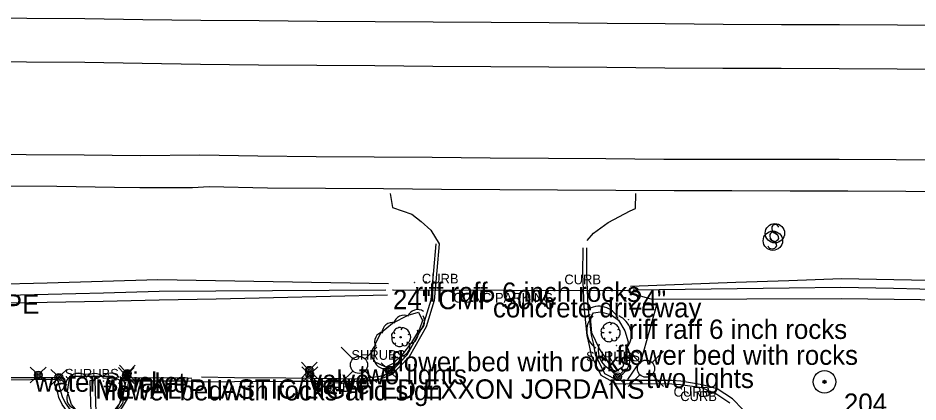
# Model space of a CAD drawing. Extents: x 1802180 to 1804859, y 572524 to 575172.
# Drawn here: x 1803724.4 to 1803957, y 573717 to 573816.1 of the extents above; entities that cross this region are included whole.
import ezdxf

# ---------------------------------------------------------------- set-up
doc = ezdxf.new("R2010")
doc.units = 0
for name, color, linetype in [('EX_EDGE_PAVEMENT', 7, 'Continuous'), ('EX_SHOULDER', 7, 'Continuous'), ('S_CURB', 7, 'Continuous'), ('S_CURB_ANNOT', 7, 'Continuous'), ('S_DITCHLINE', 7, 'Continuous'), ('S_DRG_PT_SYM', 7, 'Continuous'), ('S_IRON_PIN', 7, 'Continuous'), ('S_IRON_PIN_ANNOT', 7, 'Continuous'), ('S_MSC_PT_SYM', 7, 'Continuous'), ('S_PARKING', 7, 'Continuous'), ('S_PARKING_ANNOT', 7, 'Continuous'), ('S_PAVEMENT_CROWN', 7, 'Continuous'), ('S_SIDE_DRAIN', 7, 'Continuous'), ('S_SIDE_DRAIN_ANNOT', 7, 'Continuous'), ('S_SIGN', 7, 'Continuous'), ('S_SIGN_ANNOT', 7, 'Continuous'), ('S_SPRINKLER_HEAD', 7, 'Continuous'), ('S_SPRINKLER_HEAD_ANNOT', 7, 'Continuous'), ('S_SURVEY_TEXT_ANNOT', 7, 'Continuous'), ('S_TREE', 7, 'Continuous'), ('S_TREE_ANNOT', 7, 'Continuous'), ('S_UTILITY_POLE', 7, 'Continuous'), ('S_UTILITY_POLE_ANNOT', 7, 'Continuous')]:
    doc.layers.add(name, color=color, linetype=linetype)

msp = doc.modelspace()

# ---------------------------------------------------------------- linework, layer by layer
at = {"layer": 'EX_EDGE_PAVEMENT'}
msp.add_lwpolyline([(1803966.35, 573779.29), (1803951.36, 573779.48), (1803936.57, 573779.54), (1803921.57, 573779.58), (1803906.3, 573779.62), (1803891.3, 573779.61), (1803876.3, 573779.72), (1803861.44, 573779.87), (1803846.44, 573779.93), (1803831.45, 573780.06), (1803816.41, 573780.16), (1803801.41, 573780.27), (1803786.33, 573780.4), (1803771.33, 573780.72), (1803755.94, 573780.54), (1803741.44, 573780.69), (1803726.44, 573780.8), (1803711.44, 573780.89)], dxfattribs=at)
at = {"layer": 'EX_SHOULDER'}
for points in [[(1803508.95, 573775.06), (1803514.58, 573774.6), (1803516.31, 573774.59), (1803531.3, 573774.54), (1803546.3, 573774.46), (1803554.44, 573774.34), (1803569.39, 573774.05), (1803584.41, 573773.96), (1803599.4, 573774.12), (1803614.28, 573774.18), (1803629.34, 573773.92), (1803644.48, 573773.93), (1803659.36, 573773.87), (1803674.34, 573773.21), (1803689.36, 573773.01), (1803704.37, 573772.88), (1803719.38, 573772.78), (1803734.37, 573772.68), (1803749.34, 573772.46), (1803755.85, 573772.35), (1803769.43, 573772.35)], [(1803769.43, 573772.35), (1803773.74, 573772.62), (1803788.86, 573772.3), (1803803.86, 573772.17), (1803818.86, 573772.06), (1803833.85, 573771.95), (1803848.89, 573771.84), (1803863.84, 573771.76), (1803878.86, 573771.63), (1803893.93, 573771.54), (1803908.9, 573771.53), (1803923.9, 573771.49), (1803938.88, 573771.45), (1803953.82, 573771.37), (1803968.84, 573771.16), (1803983.86, 573771.02), (1803998.87, 573770.92), (1804013.89, 573770.83), (1804028.91, 573770.79), (1804043.8, 573770.75), (1804058.91, 573770.56), (1804073.7, 573770.51), (1804088.8, 573770.06)]]:
    msp.add_lwpolyline(points, dxfattribs=at)
at = {"layer": 'S_CURB'}
for points in [[(1803734.26, 573723.19), (1803721.06, 573723.16), (1803706.06, 573723.41), (1803697.3, 573723.24), (1803686.91, 573723.26), (1803671.91, 573723.29), (1803666.26, 573724.25), (1803659.88, 573726.28), (1803656.45, 573730.69), (1803653.84, 573736.77), (1803652.7, 573745.75), (1803652.36, 573757.72), (1803652.87, 573761.27), (1803656.21, 573764.9), (1803659.13, 573767.17), (1803663.86, 573769.14)], [(1803771.77, 573723.42), (1803780.34, 573723.29), (1803793.63, 573723.18), (1803807.28, 573723), (1803812.71, 573722.96), (1803817.98, 573723.66), (1803820.52, 573724.5), (1803824.97, 573729.14), (1803829.11, 573736.58), (1803831.15, 573743.36), (1803831.85, 573750.95), (1803832.41, 573757.83)], [(1803911.72, 573714.98), (1803909.06, 573717.79), (1803905.04, 573720.34), (1803901.22, 573721.42), (1803895.65, 573722.29), (1803893.35, 573722.47), (1803879.41, 573722.54), (1803876.03, 573724.25), (1803873.65, 573729.16), (1803873.17, 573731.78), (1803872.59, 573734.21), (1803871.73, 573741.62), (1803871.38, 573750.05), (1803871.37, 573756.78)], [(1803752.29, 573723.18), (1803767.31, 573723.3), (1803769.32, 573723.14)], [(1803734.62, 573722.43), (1803735.41, 573719.52), (1803735.75, 573718.35), (1803736.57, 573716.76), (1803738.74, 573713.7), (1803742.42, 573711.82), (1803744.94, 573711.94), (1803748.4, 573713.52), (1803750.46, 573716.24), (1803751.49, 573718), (1803752.22, 573722.06)]]:
    msp.add_lwpolyline(points, dxfattribs=at)
at = {"layer": 'S_DITCHLINE'}
for points in [[(1803882.65, 573746.87), (1803896.29, 573747.37), (1803909.93, 573747.87), (1803923.57, 573748.37), (1803937.21, 573748.87), (1803950.77, 573748.6), (1803964.33, 573748.34), (1803977.89, 573748.08), (1803991.46, 573747.82), (1804004.3, 573747.89), (1804017.14, 573747.96), (1804029.98, 573748.03), (1804042.82, 573748.1), (1804055.51, 573747.26), (1804068.19, 573746.41), (1804080.87, 573745.57), (1804093.55, 573744.72)], [(1803820.1, 573747.45), (1803805.21, 573747.71), (1803790.31, 573747.98), (1803775.41, 573748.24), (1803760.52, 573748.5), (1803746.2, 573748.09), (1803731.89, 573747.68), (1803717.57, 573747.26), (1803703.26, 573746.85), (1803683.48, 573746.78), (1803663.69, 573746.71)], [(1803883.34, 573745.94), (1803896.78, 573746.11), (1803910.21, 573746.28), (1803923.64, 573746.45), (1803937.07, 573746.63), (1803950.66, 573746.32), (1803964.25, 573746.01), (1803977.84, 573745.7), (1803991.43, 573745.39), (1804004.36, 573745.3), (1804017.29, 573745.21), (1804030.22, 573745.12), (1804043.14, 573745.03), (1804068.08, 573744.41), (1804093.03, 573743.79)], [(1803819.88, 573744.5), (1803805.12, 573744.19), (1803790.36, 573743.87), (1803775.6, 573743.55), (1803760.83, 573743.24), (1803746.39, 573742.94), (1803731.94, 573742.65), (1803717.49, 573742.35), (1803703.05, 573742.06), (1803683.66, 573742.88), (1803664.28, 573743.7)], [(1803819.4, 573745.84), (1803804.76, 573745.74), (1803790.13, 573745.65), (1803775.5, 573745.56), (1803760.86, 573745.46), (1803746.5, 573745.1), (1803732.14, 573744.73), (1803717.78, 573744.37), (1803703.42, 573744.01), (1803683.93, 573744.61), (1803664.45, 573745.21)], [(1803882.8, 573745.02), (1803888.17, 573743.49), (1803912.71, 573743.6), (1803937.24, 573743.71), (1803950.82, 573743.54), (1803964.39, 573743.37), (1803977.96, 573743.2), (1803991.54, 573743.02), (1804004.37, 573742.8), (1804017.21, 573742.57), (1804030.05, 573742.35), (1804042.88, 573742.12), (1804055.57, 573742.23), (1804068.26, 573742.33), (1804080.95, 573742.44), (1804093.63, 573742.54)], [(1803881.95, 573722.8), (1803885.48, 573727.96), (1803889.5, 573742.02)]]:
    msp.add_lwpolyline(points, dxfattribs=at)
at = {"layer": 'S_DRG_PT_SYM'}
for points in [[(1803821.27, 573745.91), (1803821.27, 573745.96), (1803821.27, 573745.91), (1803821.22, 573745.91), (1803821.27, 573745.91), (1803821.27, 573745.86), (1803821.27, 573745.91), (1803821.32, 573745.91)], [(1803882.07, 573745.77), (1803882.07, 573745.82), (1803882.07, 573745.77), (1803882.02, 573745.77), (1803882.07, 573745.77), (1803882.07, 573745.72), (1803882.07, 573745.77), (1803882.12, 573745.77)]]:
    msp.add_lwpolyline(points, dxfattribs=at)
at = {"layer": 'S_IRON_PIN'}
for radius in [2.91, 0.411, 0.262, 0.212, 0.145, 0.0822, 0.0581]:
    msp.add_circle((1803932.82, 573722.15), radius, dxfattribs=at)
at = {"layer": 'S_MSC_PT_SYM'}
for points in [[(1803826.82, 573747.82), (1803826.82, 573747.87), (1803826.82, 573747.82), (1803826.77, 573747.82), (1803826.82, 573747.82), (1803826.82, 573747.77), (1803826.82, 573747.82), (1803826.87, 573747.82)], [(1803847.12, 573743.8), (1803847.12, 573743.85), (1803847.12, 573743.8), (1803847.07, 573743.8), (1803847.12, 573743.8), (1803847.12, 573743.75), (1803847.12, 573743.8), (1803847.17, 573743.8)], [(1803882.18, 573738.24), (1803882.18, 573738.29), (1803882.18, 573738.24), (1803882.13, 573738.24), (1803882.18, 573738.24), (1803882.18, 573738.19), (1803882.18, 573738.24), (1803882.23, 573738.24)], [(1803879.04, 573731.55), (1803879.04, 573731.6), (1803879.04, 573731.55), (1803878.99, 573731.55), (1803879.04, 573731.55), (1803879.04, 573731.5), (1803879.04, 573731.55), (1803879.09, 573731.55)], [(1803820.72, 573729.86), (1803820.72, 573729.91), (1803820.72, 573729.86), (1803820.67, 573729.86), (1803820.72, 573729.86), (1803820.72, 573729.81), (1803820.72, 573729.86), (1803820.77, 573729.86)], [(1803728.7, 573724.59), (1803728.7, 573724.64), (1803728.7, 573724.59), (1803728.65, 573724.59), (1803728.7, 573724.59), (1803728.7, 573724.54), (1803728.7, 573724.59), (1803728.75, 573724.59)], [(1803744.35, 573722.8), (1803744.35, 573722.85), (1803744.35, 573722.8), (1803744.3, 573722.8), (1803744.35, 573722.8), (1803744.35, 573722.75), (1803744.35, 573722.8), (1803744.4, 573722.8)], [(1803746.44, 573722.36), (1803746.44, 573722.41), (1803746.44, 573722.36), (1803746.39, 573722.36), (1803746.44, 573722.36), (1803746.44, 573722.31), (1803746.44, 573722.36), (1803746.49, 573722.36)]]:
    msp.add_lwpolyline(points, dxfattribs=at)
at = {"layer": 'S_PARKING'}
for points in [[(1803734.26, 573722.73), (1803721.05, 573722.61), (1803706.08, 573722.69), (1803697.3, 573722.48), (1803686.91, 573722.63), (1803671.8, 573722.68), (1803665.93, 573723.25), (1803659.23, 573725.79), (1803655.81, 573730.2), (1803653.17, 573736.5), (1803651.97, 573745.68), (1803651.65, 573757.71), (1803651.9, 573760.39), (1803652.12, 573761.37), (1803655.69, 573765.38), (1803658.73, 573767.69), (1803664.04, 573769.76), (1803664.33, 573772.53)], [(1803820.52, 573770.79), (1803821.18, 573767.21), (1803826.12, 573765.42), (1803828.59, 573763.58), (1803831.04, 573761.35), (1803833.22, 573757.77), (1803832.65, 573750.89), (1803831.92, 573743.14), (1803829.83, 573736.38), (1803825.5, 573728.64), (1803821.04, 573724.01), (1803818.08, 573722.87), (1803812.81, 573722.16), (1803807.27, 573722.22), (1803793.62, 573722.26), (1803780.33, 573722.15), (1803771.74, 573722.07), (1803769.24, 573722.24), (1803767.73, 573722.29), (1803752.82, 573722.31), (1803752.77, 573720.94), (1803752.57, 573717.81), (1803751.31, 573715.59)], [(1803820.52, 573770.79), (1803821.18, 573767.21), (1803826.12, 573765.42), (1803828.59, 573763.58), (1803831.04, 573761.35), (1803833.22, 573757.77)], [(1803871.44, 573758.7), (1803873.08, 573760.57), (1803876.89, 573763.31), (1803882.59, 573766.33), (1803883.96, 573766.89), (1803884.08, 573770.79)], [(1803871.44, 573758.7), (1803873.08, 573760.57), (1803876.89, 573763.31), (1803882.59, 573766.33), (1803883.96, 573766.89), (1803884.08, 573770.79)], [(1803833.22, 573757.77), (1803832.65, 573750.89), (1803831.92, 573743.14), (1803829.83, 573736.38), (1803825.5, 573728.64), (1803821.04, 573724.01), (1803818.08, 573722.87), (1803812.81, 573722.16), (1803807.27, 573722.22), (1803793.62, 573722.26), (1803780.33, 573722.15), (1803771.74, 573722.07)], [(1803908.32, 573716.62), (1803904.69, 573719.08), (1803901.1, 573720.62), (1803895.58, 573721.39), (1803893.36, 573721.54), (1803878.94, 573721.66), (1803875.07, 573723.81), (1803872.63, 573729), (1803872.09, 573731.56), (1803871.47, 573734.1), (1803870.73, 573741.59), (1803870.39, 573750.06), (1803870.43, 573756.78)], [(1803908.32, 573716.62), (1803904.69, 573719.08), (1803901.1, 573720.62), (1803895.58, 573721.39), (1803893.36, 573721.54), (1803878.94, 573721.66), (1803875.07, 573723.81), (1803872.63, 573729), (1803872.09, 573731.56), (1803871.47, 573734.1), (1803870.73, 573741.59), (1803870.39, 573750.06), (1803870.43, 573756.78)], [(1803735.79, 573716.34), (1803734.96, 573718.12), (1803734.66, 573719.3), (1803733.8, 573721.64), (1803734.26, 573722.73), (1803721.05, 573722.61)], [(1803752.77, 573720.94), (1803752.57, 573717.81), (1803751.31, 573715.59), (1803749.22, 573712.89), (1803744.96, 573711.13), (1803742.43, 573710.89), (1803738.32, 573712.87), (1803735.79, 573716.34), (1803734.96, 573718.12), (1803734.66, 573719.3), (1803733.8, 573721.64), (1803734.26, 573722.73)], [(1803771.74, 573722.07), (1803769.24, 573722.24), (1803767.73, 573722.29), (1803752.82, 573722.31), (1803752.77, 573720.94)]]:
    msp.add_lwpolyline(points, dxfattribs=at)
at = {"layer": 'S_PAVEMENT_CROWN'}
for points in [[(1803966.66, 573814.15), (1803951.66, 573814.28), (1803936.66, 573814.34), (1803921.66, 573814.38), (1803906.66, 573814.43), (1803891.66, 573814.58), (1803876.66, 573814.73), (1803861.66, 573814.86), (1803846.66, 573814.95), (1803831.66, 573815.05), (1803816.66, 573815.15), (1803801.66, 573815.26), (1803786.66, 573815.37), (1803771.66, 573815.52), (1803756.67, 573815.66), (1803741.67, 573815.93), (1803726.67, 573816.02), (1803711.67, 573816.12)], [(1803711.6, 573804.93), (1803726.6, 573804.83), (1803741.6, 573804.7), (1803756.43, 573804.47), (1803771.56, 573804.16), (1803786.56, 573804.06), (1803801.58, 573803.94), (1803816.58, 573803.83), (1803831.59, 573803.72), (1803846.59, 573803.6), (1803861.59, 573803.54), (1803876.55, 573803.39), (1803891.54, 573803.23), (1803906.54, 573803.17), (1803921.63, 573803.13), (1803936.63, 573803.09), (1803951.56, 573803.03), (1803966.56, 573802.86)]]:
    msp.add_lwpolyline(points, dxfattribs=at)
at = {"layer": 'S_SIDE_DRAIN'}
msp.add_line((1803821.27, 573745.91), (1803882.07, 573745.77), dxfattribs=at)
at = {"layer": 'S_SIGN'}
msp.add_lwpolyline([(1803744.22, 573722.6), (1803744.45, 573714.23), (1803743.24, 573714.21), (1803743.03, 573722.52), (1803744.22, 573722.6)], dxfattribs=at)
for centre in [(1803919.99, 573760.54), (1803919.47, 573758.6)]:
    msp.add_circle(centre, 2.5, dxfattribs=at)
for centre, radius, start, end in [((1803920.07, 573761.81), 0.952, 16.5258, 156.8957), ((1803920.15, 573759.93), 1.51, 167.1196, 241.9813), ((1803919.54, 573759.87), 0.952, 16.5258, 156.8957), ((1803920.68, 573761.87), 1.51, 167.1196, 241.9813), ((1803919.58, 573759.2), 1.4, 358.6529, 73.7063), ((1803919.84, 573759.72), 1.28, 204.641, 335.359), ((1803919.05, 573757.26), 1.4, 358.6529, 73.7063), ((1803919.31, 573757.78), 1.28, 204.641, 335.359)]:
    msp.add_arc(centre, radius, start, end, dxfattribs=at)
at = {"layer": 'S_SPRINKLER_HEAD'}
for p, q in [((1803728.89, 573724.62), (1803727.55, 573725.97)), ((1803730.29, 573724.62), (1803731.64, 573725.97)), ((1803734.22, 573724.04), (1803732.87, 573725.38)), ((1803735.62, 573724.04), (1803736.96, 573725.38)), ((1803751.64, 573724.51), (1803750.3, 573725.85)), ((1803751.93, 573725.08), (1803750.59, 573726.42)), ((1803753.05, 573724.51), (1803754.39, 573725.85)), ((1803753.34, 573725.08), (1803754.68, 573726.42)), ((1803798.94, 573725.86), (1803797.6, 573727.21)), ((1803799.08, 573724.71), (1803797.73, 573726.06)), ((1803800.35, 573725.86), (1803801.69, 573727.21)), ((1803800.48, 573724.71), (1803801.82, 573726.06)), ((1803819.61, 573725.75), (1803818.26, 573727.09)), ((1803821.01, 573725.75), (1803822.35, 573727.09)), ((1803878.62, 573724.17), (1803877.28, 573725.51)), ((1803880.03, 573724.17), (1803881.37, 573725.51)), ((1803728.89, 573723.22), (1803727.55, 573721.88)), ((1803730.29, 573723.22), (1803731.64, 573721.88)), ((1803751.64, 573723.11), (1803750.3, 573721.76)), ((1803751.93, 573723.67), (1803750.59, 573722.33)), ((1803753.05, 573723.11), (1803754.39, 573721.76)), ((1803753.34, 573723.67), (1803754.68, 573722.33)), ((1803798.94, 573724.46), (1803797.6, 573723.12)), ((1803799.08, 573723.31), (1803797.73, 573721.96)), ((1803800.35, 573724.46), (1803801.69, 573723.12)), ((1803800.48, 573723.31), (1803801.82, 573721.96)), ((1803819.61, 573724.34), (1803818.26, 573723)), ((1803821.01, 573724.34), (1803822.35, 573723)), ((1803734.22, 573722.64), (1803732.87, 573721.29)), ((1803735.62, 573722.64), (1803736.96, 573721.29)), ((1803878.62, 573722.76), (1803877.28, 573721.42)), ((1803880.03, 573722.76), (1803881.37, 573721.42))]:
    msp.add_line(p, q, dxfattribs=at)
for centre, radius in [((1803752.64, 573724.38), 0.994), ((1803799.64, 573725.16), 0.994), ((1803799.64, 573725.16), 0.634), ((1803799.64, 573725.16), 0.274), ((1803820.31, 573725.04), 0.994), ((1803820.31, 573725.04), 0.634), ((1803729.59, 573723.92), 0.994), ((1803729.59, 573723.92), 0.634), ((1803729.59, 573723.92), 0.274), ((1803734.92, 573723.34), 0.994), ((1803734.92, 573723.34), 0.634), ((1803734.92, 573723.34), 0.274), ((1803752.35, 573723.81), 0.994), ((1803752.35, 573723.81), 0.634), ((1803752.64, 573724.38), 0.634), ((1803752.35, 573723.81), 0.274), ((1803752.64, 573724.38), 0.274), ((1803799.78, 573724.01), 0.994), ((1803799.78, 573724.01), 0.634), ((1803799.78, 573724.01), 0.274), ((1803820.31, 573725.04), 0.274), ((1803879.32, 573723.46), 0.994), ((1803879.32, 573723.46), 0.634), ((1803879.32, 573723.46), 0.274)]:
    msp.add_circle(centre, radius, dxfattribs=at)
at = {"layer": 'S_TREE'}
for p, q in [((1803877.7, 573737.26), (1803877.48, 573736.79)), ((1803821.46, 573734.9), (1803821.74, 573734.58)), ((1803823.55, 573736.02), (1803823.34, 573735.55)), ((1803875.24, 573734.86), (1803875.86, 573734.86)), ((1803875.6, 573736.15), (1803875.88, 573735.82)), ((1803879.66, 573735.72), (1803879.3, 573735.57)), ((1803821.1, 573733.62), (1803821.72, 573733.62)), ((1803825.09, 573732.21), (1803824.84, 573732.45)), ((1803825.52, 573734.48), (1803825.16, 573734.33)), ((1803875.88, 573733.11), (1803876.13, 573733.49)), ((1803877.91, 573732.96), (1803877.87, 573733.39)), ((1803879.23, 573733.45), (1803878.98, 573733.69)), ((1803821.74, 573731.87), (1803821.99, 573732.25)), ((1803823.77, 573731.72), (1803823.73, 573732.15))]:
    msp.add_line(p, q, dxfattribs=at)
for points in [[(1803816.34, 573727.42), (1803816.65, 573731.85), (1803818.23, 573734.92), (1803821.14, 573737.31), (1803825.22, 573739.36), (1803827.84, 573740.19), (1803828.93, 573737.96), (1803828.17, 573735.76), (1803826.04, 573732.34), (1803823.6, 573729.01), (1803821.29, 573726.89), (1803819.45, 573725.97), (1803816.34, 573727.42)], [(1803878.55, 573724.57), (1803876.46, 573728.05), (1803874.67, 573730.71), (1803872.71, 573734.79), (1803872.34, 573738.75), (1803873.11, 573739.96), (1803874.92, 573740.27), (1803877.55, 573739.56), (1803879.54, 573738.11), (1803881.24, 573735.32), (1803882.03, 573732.48), (1803880.73, 573726.05), (1803878.55, 573724.57)], [(1803737.79, 573723.61), (1803748.81, 573723.59), (1803751.1, 573722.32), (1803751.47, 573719.6), (1803750.62, 573716.58), (1803749.13, 573713.9), (1803742.37, 573713.13), (1803739.74, 573714.49), (1803738.18, 573716.29), (1803737.12, 573719.64), (1803737.79, 573723.61)]]:
    msp.add_lwpolyline(points, dxfattribs=at)
for centre in [(1803877.39, 573734.91), (1803823.25, 573733.67)]:
    msp.add_circle(centre, 0.188, dxfattribs=at)
for centre, radius, start, end in [((1803874.56, 573736.32), 5.35, 23.9843, 125.5812), ((1803824.19, 573736.63), 2.74, 65.8801, 167.4771), ((1803827.67, 573738.07), 2.74, 56.8574, 158.4543), ((1803821.2, 573734.77), 2.74, 78.5236, 180.1205), ((1803826.73, 573737.72), 2.74, 290.1168, 31.7137), ((1803876.69, 573735.35), 5.35, 134.5266, 236.1235), ((1803877.53, 573734.26), 5.35, 324.8119, 66.4088), ((1803819.25, 573732.41), 2.74, 102.0316, 203.6285), ((1803825.04, 573734.62), 2.74, 277.2267, 18.8236), ((1803818.48, 573729.39), 2.74, 125.1156, 226.7125), ((1803822.91, 573731.45), 2.74, 273.0458, 14.6427), ((1803879.65, 573730.3), 5.35, 163.0331, 264.63), ((1803877.25, 573728.28), 5.35, 297.8039, 39.4008), ((1803820.49, 573728.82), 2.74, 261.7777, 3.3746), ((1803819.09, 573728.31), 2.74, 194.279, 295.8759), ((1803739.45, 573721.09), 2.85, 119.6904, 221.2873), ((1803739.99, 573721.53), 2.85, 39.1092, 140.7061), ((1803744.17, 573721.46), 2.85, 39.1092, 140.7061), ((1803748.3, 573721.51), 2.85, 39.1092, 140.7061), ((1803749.2, 573721.03), 2.85, 316.7937, 58.3907), ((1803739.81, 573717.93), 2.85, 146.6596, 248.2565), ((1803748.8, 573717.71), 2.85, 293.6114, 35.2083)]:
    msp.add_arc(centre, radius, start, end, dxfattribs=at)
for centre, major_axis, ratio, start_param, end_param in [((1803876.65, 573736.68), (1.02, 0.6), 0.471018, 0, 3.141593), ((1803878.67, 573736.5), (-1, 0.75), 0.405113, 3.141593, 6.283186), ((1803821.28, 573734.27), (0.168, 0.567), 0.646762, 0, 3.141593), ((1803822.51, 573735.44), (1.02, 0.6), 0.471018, 0, 3.141593), ((1803824.53, 573735.26), (-1, 0.75), 0.405113, 3.141593, 6.283186), ((1803875.42, 573735.51), (0.168, 0.567), 0.646762, 0, 3.141593), ((1803875.59, 573734.05), (-0.337, 0.88), 0.420543, 6.283185, 9.424777), ((1803879.41, 573734.62), (0.25, 1.13), 0.482994, 3.141593, 6.283185), ((1803821.45, 573732.81), (-0.337, 0.88), 0.420543, 6.283185, 9.424777), ((1803825.27, 573733.38), (0.25, 1.13), 0.482994, 3.141593, 6.283185), ((1803876.94, 573733.07), (-1.01, 0.11), 0.529943, 0, 3.141593), ((1803878.57, 573733.23), (0.602, 0.255), 0.711534, 3.141592, 6.283185), ((1803822.8, 573731.83), (-1.01, 0.11), 0.529943, 0, 3.141593), ((1803824.43, 573731.99), (0.602, 0.255), 0.711534, 3.141592, 6.283185)]:
    msp.add_ellipse(centre, major_axis=major_axis, ratio=ratio, start_param=start_param, end_param=end_param, dxfattribs=at)
at = {"layer": 'S_UTILITY_POLE'}
for p, q in [((1803810.91, 573728.11), (1803807.92, 573731.09)), ((1803814.09, 573728.11), (1803817.07, 573731.09)), ((1803885.08, 573727.14), (1803882.1, 573730.12)), ((1803888.26, 573727.14), (1803891.24, 573730.12)), ((1803810.91, 573724.93), (1803807.92, 573721.95)), ((1803814.09, 573724.93), (1803817.07, 573721.95)), ((1803885.08, 573723.96), (1803882.1, 573720.98)), ((1803888.26, 573723.96), (1803891.24, 573720.98))]:
    msp.add_line(p, q, dxfattribs=at)
for centre in [(1803812.5, 573726.53), (1803886.68, 573725.56)]:
    msp.add_circle(centre, 2.21, dxfattribs=at)

# ---------------------------------------------------------------- texts
at = {"layer": 'S_CURB_ANNOT'}
for p in [(1803828.75, 573747.56), (1803865.58, 573747.36), (1803800.86, 573719.57), (1803893.8, 573718.33), (1803895.53, 573717.19)]:
    msp.add_text('CURB', height=2.5, dxfattribs=at).set_placement(p)
at = {"layer": 'S_IRON_PIN_ANNOT'}
msp.add_text('204', height=5, dxfattribs=at).set_placement((1803937.82, 573714.15))
at = {"layer": 'S_PARKING_ANNOT'}
msp.add_text('CONC PARKING', height=2.5, dxfattribs=at).set_placement((1803836.87, 573742.63))
at = {"layer": 'S_SIDE_DRAIN_ANNOT'}
for s, p in [('24" CMP 30%', (1803821.27, 573740.91)), ('24"       ', (1803882.07, 573740.77))]:
    msp.add_text(s, height=5, dxfattribs=at).set_placement(p)
at = {"layer": 'S_SIGN_ANNOT'}
msp.add_text('METAL/PLASTIC/LIGHTED EXXON JORDANS  ', height=5, dxfattribs=at).set_placement((1803744.35, 573717.8))
at = {"layer": 'S_SPRINKLER_HEAD'}
for p in [(1803729.55, 573723.87), (1803734.88, 573723.29), (1803752.3, 573723.76), (1803752.59, 573724.33), (1803799.6, 573725.11), (1803799.74, 573723.96), (1803820.27, 573724.99), (1803879.28, 573723.41)]:
    msp.add_text('+', height=0.1, dxfattribs=at).set_placement(p)
at = {"layer": 'S_SPRINKLER_HEAD_ANNOT'}
for p in [(1803799.64, 573720.16), (1803752.64, 573719.38), (1803799.78, 573719.01)]:
    msp.add_text('valve', height=5, dxfattribs=at).set_placement(p)
at = {"layer": 'S_SURVEY_TEXT_ANNOT'}
for s, p in [('riff raff  6 inch rocks', (1803826.82, 573742.82)), ('ROCK RIP RAP SLOPE', (1803657.79, 573739.75)), ('concrete driveway', (1803847.12, 573738.8)), ('riff raff 6 inch rocks', (1803882.18, 573733.24)), ('flower bed with rocks', (1803820.72, 573724.86)), ('flower bed with rocks', (1803879.04, 573726.55)), ('water spicket', (1803728.7, 573719.59)), ('flower bedwith rocks and sign', (1803746.44, 573717.36))]:
    msp.add_text(s, height=5, dxfattribs=at).set_placement(p)
at = {"layer": 'S_TREE_ANNOT'}
for p in [(1803810.54, 573727.84), (1803871.18, 573727.47), (1803736.49, 573723)]:
    msp.add_text('SHRUBS', height=2.5, dxfattribs=at).set_placement(p)
at = {"layer": 'S_UTILITY_POLE_ANNOT'}
for p in [(1803812.5, 573721.53), (1803886.68, 573720.56)]:
    msp.add_text('two lights', height=5, dxfattribs=at).set_placement(p)

doc.saveas('drawing.dxf')
